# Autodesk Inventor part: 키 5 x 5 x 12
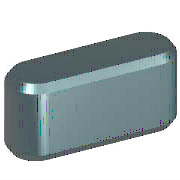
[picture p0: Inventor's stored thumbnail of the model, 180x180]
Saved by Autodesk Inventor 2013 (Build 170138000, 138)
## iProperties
Created: 2012-02
Part Number: 키 5 x 5 x 12
Material: 강철, 연강
Description: 키 및 해당 키홈
Document SubType Name: Modeling
Standard: KS B 1311
Designer: mduedu
Standards Organization: KS
Language: ko-KR
Size Designation: 5 x 5 x 12
Categories: <MemberInstance><Categories><Category DisplayName="샤프트 부품" InternalName="7f7aeb1f-a693-4053-b835-cee3144e0d98" Mnemonic="SHFT"><Category DisplayName="키" Interna
Density: 7.86 g/cm^3
Mass: 2.11085 g
Surface Area: 2.43471 cm^2
Volume: 0.268556 cm^3
IsCustomPart: 1
Author: mduedu
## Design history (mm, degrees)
workplane "Work Plane1"
workplane "Work Plane2"
sketch "스케치1"
  geometry: L1 (2.5, 2.5)-(9.5, 2.5); L2 (9.5, -2.5)-(2.5, -2.5); L3 (0, 9.4)-(0, -7.4) reference; L4 (-5, 0)-(30, 0) reference; L5 (12, 0)-(12, 7); A1 r 2.5 centre (2.5, 0) between (2.5, 2.5) and (2.5, -2.5); A2 r 2.5 centre (9.5, 0) between (9.5, -2.5) and (9.5, 2.5)
  constraints: 6 end point, 5 point on circle, 4 tangent, 3 point on line, 2 centre point, 1 horizontal, 1 parallel, 1 perpendicular
  dimensions: "d0" = 2.5 radius of A1 (= 0.5 x PB); "d13" = 2.5 radius of A2 (= 0.5 x PB); "d14" = 12 distance between parallel lines of L5 L3 (= NLG)
extrude "본체1" new body sketch "스케치1" taper "d3" = 0 deg; stored distance "d4" = 10
workplane "Work Plane3"
body "Solid1"
chamfer "모따기1" distance "d8" = 0.4 (= PHH); stored, may be unused: second distance "d9" = 0.4 (= PHH), angle "d15" = 45 deg
other parameters: "d1" = -3 (= -PNT), "d2" = 2 (= PH - PNT), "NLG" = 12 [user parameter; used in 3 equation terms], "PB" = 5 [user parameter; used in 2 equation terms], "PNT" = 3 [user parameter; used in 2 equation terms], "PH" = 5 [user parameter; used in 1 equation term], "PHH" = 0.4 [user parameter; used in 2 equation terms], "d10" = 0, "d16" = 0, "d17" = 0, "d18" = 0, "WDMIN" = 12 [user parameter], "PLB2" = 12 (= NLG) [user parameter], "WDMAX" = 17 [user parameter], "PLB1" = 12 (= NLG) [user parameter], "RR" = 0.16 [user parameter], "PUEB" = 2.3 [user parameter]
